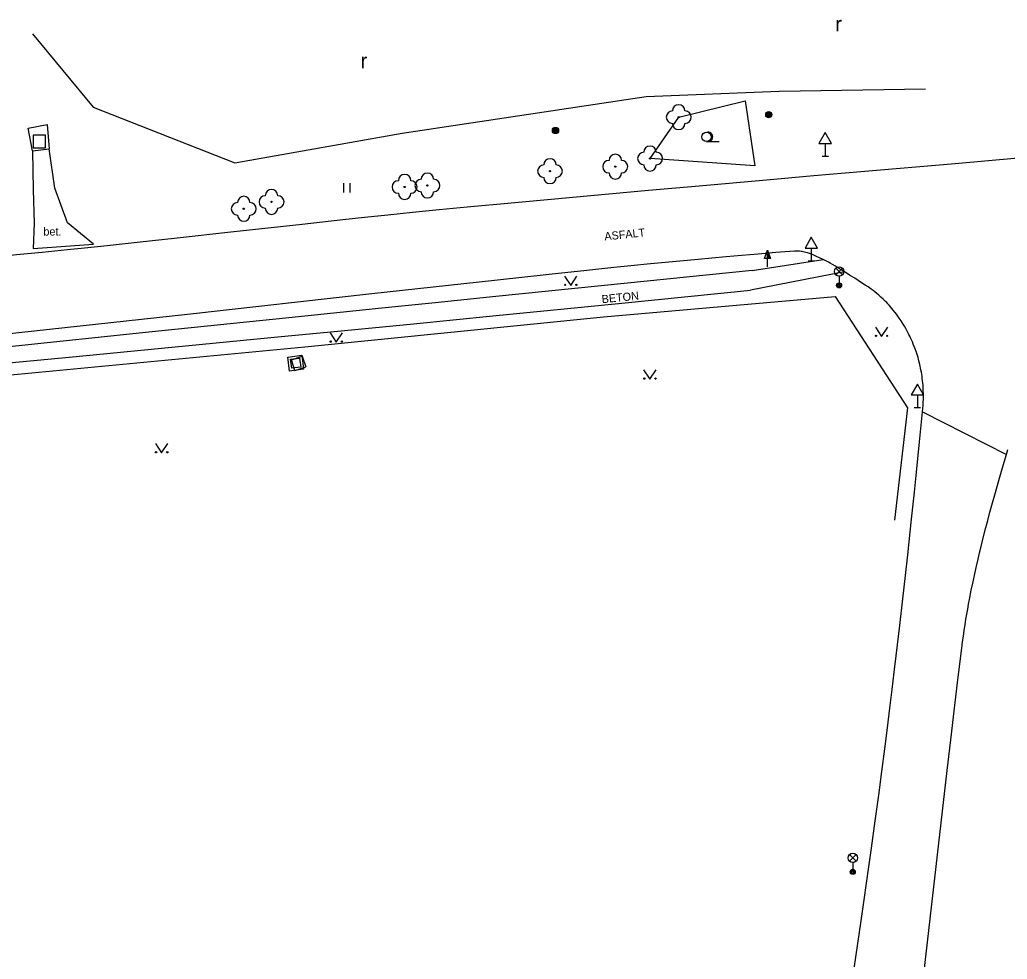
# Model space of a CAD drawing. Extents: x -541281 to -539153, y -1183881 to -1182141.
# Drawn here: x -539932.5 to -539853.2, y -1183251.4 to -1183176.1 of the extents above; entities that cross this region are included whole.
import ezdxf

# ---------------------------------------------------------------- set-up
doc = ezdxf.new("R2010")
doc.units = 0
for name, color, linetype in [('Vrstva 10', 7, 'Continuous'), ('Vrstva 11', 7, 'Continuous'), ('Vrstva 21', 7, 'Continuous'), ('Vrstva 22', 7, 'Continuous'), ('Vrstva 23', 7, 'Continuous'), ('Vrstva 25', 7, 'Continuous'), ('Vrstva 26', 7, 'Continuous'), ('Vrstva 33', 7, 'Continuous'), ('Vrstva 34', 7, 'Continuous'), ('Vrstva 36', 7, 'Continuous'), ('Vrstva 40', 7, 'Continuous'), ('Vrstva 7', 7, 'Continuous')]:
    doc.layers.add(name, color=color, linetype=linetype)

msp = doc.modelspace()

# ---------------------------------------------------------------- linework, layer by layer
at = {"layer": 'Vrstva 10'}
for p, q in [((-539852.324, -1183187.172), (-539857.371, -1183187.609)), ((-539857.371, -1183187.609), (-539864.941, -1183188.26)), ((-539872.51, -1183188.92), (-539877.926, -1183189.401)), ((-539877.926, -1183189.401), (-539881.987, -1183189.764)), ((-539888.079, -1183190.314), (-539894.17, -1183190.87)), ((-539881.987, -1183189.764), (-539888.079, -1183190.314)), ((-539909.795, -1183192.471), (-539915.522, -1183193.103)), ((-539883.41, -1183195.806), (-539884.78, -1183195.946)), ((-539894.36, -1183196.97), (-539904.21, -1183198.056)), ((-539904.21, -1183198.056), (-539918.985, -1183199.692)), ((-539918.985, -1183199.692), (-539926.372, -1183200.508)), ((-539926.372, -1183200.508), (-539933.76, -1183201.32)), ((-539910.943, -1183203.121), (-539909.821, -1183202.977)), ((-539910.799, -1183204.243), (-539910.943, -1183203.121)), ((-539910.719, -1183203.294), (-539909.994, -1183203.201)), ((-539909.994, -1183203.201), (-539909.901, -1183203.926)), ((-539909.821, -1183202.977), (-539909.677, -1183204.099)), ((-539910.626, -1183204.019), (-539910.719, -1183203.294)), ((-539909.901, -1183203.926), (-539910.626, -1183204.019)), ((-539909.677, -1183204.099), (-539910.799, -1183204.243)), ((-539860.649, -1183213.97), (-539860.481, -1183212.354)), ((-539861.822, -1183224.66), (-539861.577, -1183222.515)), ((-539863.029, -1183234.571), (-539862.813, -1183232.881)), ((-539859.898, -1183252.651), (-539858.404, -1183239.563))]:
    msp.add_line(p, q, dxfattribs=at)
for points in [[(-539864.941, -1183188.26), (-539868.726, -1183188.588), (-539872.51, -1183188.92)], [(-539894.17, -1183190.87), (-539895.376, -1183190.982), (-539896.544, -1183191.093), (-539898.806, -1183191.314), (-539900.926, -1183191.527), (-539902.913, -1183191.733)], [(-539902.913, -1183191.733), (-539904.776, -1183191.929), (-539906.522, -1183192.116), (-539909.795, -1183192.471)], [(-539915.522, -1183193.103), (-539919.817, -1183193.577), (-539923.039, -1183193.927), (-539925.456, -1183194.185)], [(-539925.456, -1183194.185), (-539927.269, -1183194.375), (-539928.629, -1183194.514), (-539930.669, -1183194.72), (-539932.71, -1183194.92), (-539934.224, -1183195.064)], [(-539874.518, -1183194.967), (-539875.758, -1183195.076), (-539876.921, -1183195.181), (-539878.012, -1183195.281), (-539880.056, -1183195.475), (-539881.845, -1183195.65), (-539883.41, -1183195.806)], [(-539865.851, -1183196.545), (-539866.06, -1183196.413), (-539866.27, -1183196.28), (-539866.48, -1183196.146), (-539866.662, -1183196.031), (-539866.981, -1183195.835), (-539867.223, -1183195.693), (-539867.407, -1183195.588), (-539867.547, -1183195.512), (-539867.76, -1183195.399), (-539867.98, -1183195.29), (-539868.26, -1183195.156), (-539868.506, -1183195.041), (-539868.723, -1183194.946), (-539868.913, -1183194.869), (-539869.081, -1183194.808), (-539869.229, -1183194.759), (-539869.358, -1183194.721), (-539869.472, -1183194.692), (-539869.572, -1183194.67), (-539869.659, -1183194.654), (-539869.736, -1183194.641), (-539869.871, -1183194.625), (-539869.973, -1183194.617), (-539870.049, -1183194.614), (-539870.165, -1183194.614), (-539870.28, -1183194.62), (-539871.784, -1183194.739), (-539873.195, -1183194.855), (-539874.518, -1183194.967)], [(-539884.78, -1183195.946), (-539887.176, -1183196.195), (-539888.973, -1183196.385), (-539891.667, -1183196.676), (-539894.36, -1183196.97)], [(-539860.124, -1183204.159), (-539860.154, -1183204.003), (-539860.186, -1183203.851), (-539860.22, -1183203.705), (-539860.29, -1183203.422), (-539860.363, -1183203.157), (-539860.438, -1183202.91), (-539860.514, -1183202.68), (-539860.59, -1183202.464), (-539860.666, -1183202.263), (-539860.741, -1183202.075), (-539860.815, -1183201.899), (-539860.887, -1183201.735), (-539860.958, -1183201.582), (-539861.027, -1183201.438), (-539861.093, -1183201.304), (-539861.224, -1183201.054), (-539861.344, -1183200.837), (-539861.454, -1183200.647), (-539861.554, -1183200.482), (-539861.644, -1183200.339), (-539861.725, -1183200.213), (-539861.872, -1183199.995), (-539861.986, -1183199.833), (-539862.074, -1183199.711), (-539862.21, -1183199.53), (-539862.35, -1183199.35), (-539862.46, -1183199.215), (-539862.567, -1183199.087), (-539862.672, -1183198.968), (-539862.775, -1183198.856), (-539862.875, -1183198.75), (-539862.972, -1183198.65), (-539863.067, -1183198.556), (-539863.16, -1183198.467), (-539863.341, -1183198.301), (-539863.513, -1183198.151), (-539863.675, -1183198.016), (-539863.829, -1183197.893), (-539863.975, -1183197.782), (-539864.112, -1183197.68), (-539864.372, -1183197.495), (-539864.602, -1183197.338), (-539864.805, -1183197.204), (-539865.164, -1183196.973), (-539865.437, -1183196.802), (-539865.851, -1183196.545)], [(-539860.481, -1183212.354), (-539860.233, -1183209.932), (-539859.99, -1183207.51), (-539859.966, -1183207.246), (-539859.949, -1183206.991), (-539859.937, -1183206.743), (-539859.93, -1183206.504), (-539859.928, -1183206.271), (-539859.93, -1183206.046), (-539859.936, -1183205.829), (-539859.946, -1183205.618), (-539859.96, -1183205.414), (-539859.976, -1183205.216), (-539859.995, -1183205.025), (-539860.017, -1183204.84), (-539860.041, -1183204.662), (-539860.066, -1183204.489), (-539860.094, -1183204.321), (-539860.124, -1183204.159)], [(-539855.674, -1183219.912), (-539855.544, -1183219.349), (-539855.419, -1183218.822), (-539855.298, -1183218.328), (-539855.184, -1183217.865), (-539854.962, -1183216.999), (-539854.763, -1183216.241), (-539854.585, -1183215.579), (-539854.426, -1183214.999), (-539854.143, -1183213.985), (-539853.926, -1183213.224), (-539853.596, -1183212.083), (-539853.26, -1183210.94), (-539853.14, -1183210.542)], [(-539861.577, -1183222.515), (-539861.367, -1183220.639), (-539861.186, -1183218.997), (-539860.876, -1183216.124), (-539860.649, -1183213.97)], [(-539856.231, -1183222.573), (-539856.088, -1183221.84), (-539855.946, -1183221.154), (-539855.808, -1183220.513), (-539855.674, -1183219.912)], [(-539857.521, -1183231.998), (-539857.189, -1183229.239), (-539856.85, -1183226.48), (-539856.786, -1183225.986), (-539856.721, -1183225.508), (-539856.653, -1183225.046), (-539856.584, -1183224.599), (-539856.515, -1183224.166), (-539856.444, -1183223.748), (-539856.373, -1183223.343), (-539856.302, -1183222.952), (-539856.231, -1183222.573)], [(-539862.813, -1183232.881), (-539862.615, -1183231.296), (-539862.433, -1183229.81), (-539862.264, -1183228.417), (-539862.109, -1183227.11), (-539861.822, -1183224.66)], [(-539858.404, -1183239.563), (-539858.026, -1183236.291), (-539857.738, -1183233.838), (-539857.521, -1183231.998)], [(-539864.26, -1183243.65), (-539864.1, -1183242.524), (-539863.796, -1183240.341), (-539863.517, -1183238.293), (-539863.263, -1183236.372), (-539863.029, -1183234.571)], [(-539865.618, -1183253.1), (-539864.938, -1183248.375), (-539864.26, -1183243.65)]]:
    msp.add_lwpolyline(points, dxfattribs=at)
at = {"layer": 'Vrstva 11'}
for p, q in [((-539873.68, -1183196.18), (-539867.98, -1183195.29)), ((-539873.68, -1183196.18), (-539883.96, -1183197.22)), ((-539866.27, -1183196.28), (-539873.81, -1183197.76)), ((-539883.96, -1183197.22), (-539894.24, -1183198.26)), ((-539884.145, -1183198.79), (-539873.81, -1183197.76)), ((-539903.396, -1183199.194), (-539910.872, -1183199.965)), ((-539894.48, -1183199.82), (-539884.145, -1183198.79)), ((-539910.872, -1183199.965), (-539922.086, -1183201.129)), ((-539907.229, -1183201.072), (-539900.854, -1183200.45)), ((-539922.086, -1183201.129), (-539933.3, -1183202.29)), ((-539928.482, -1183203.12), (-539911.48, -1183201.483)), ((-539911.48, -1183201.483), (-539907.229, -1183201.072)), ((-539933.34, -1183203.59), (-539928.482, -1183203.12)), ((-539859.99, -1183207.51), (-539853.26, -1183210.94))]:
    msp.add_line(p, q, dxfattribs=at)
for points in [[(-539931.43, -1183186.58), (-539931.79, -1183184.75), (-539930.27, -1183184.46), (-539930.1, -1183186.41)], [(-539931.43, -1183186.58), (-539930.1, -1183186.41)], [(-539931.43, -1183186.58), (-539931.37, -1183189.69), (-539931.3, -1183192.38), (-539931.37, -1183194.4), (-539926.55, -1183194.05), (-539928.63, -1183192.35), (-539929.64, -1183189.56), (-539930.1, -1183186.41)], [(-539894.24, -1183198.26), (-539899.123, -1183198.756), (-539903.396, -1183199.194)], [(-539900.854, -1183200.45), (-539897.667, -1183200.136), (-539894.48, -1183199.82)]]:
    msp.add_lwpolyline(points, dxfattribs=at)
at = {"layer": 'Vrstva 21'}
msp.add_lwpolyline([(-539879.57, -1183183.87), (-539874.24, -1183182.55), (-539873.46, -1183187.77), (-539881.87, -1183187.19), (-539879.57, -1183183.87)], dxfattribs=at)
at = {"layer": 'Vrstva 22'}
for centre in [(-539879.57, -1183183.87), (-539881.87, -1183187.19), (-539884.66, -1183187.84), (-539889.9, -1183188.2), (-539901.57, -1183189.47), (-539899.74, -1183189.35), (-539914.48, -1183191.22), (-539912.25, -1183190.67)]:
    msp.add_circle(centre, 0.05, dxfattribs=at)
for centre, start, end in [((-539880.07, -1183183.87), 90, 270), ((-539879.57, -1183183.37), 0, 180), ((-539879.07, -1183183.87), 270, 90), ((-539879.57, -1183184.37), 180, 0), ((-539881.87, -1183186.69), 0, 180), ((-539889.9, -1183187.7), 0, 180), ((-539885.16, -1183187.84), 90, 270), ((-539884.66, -1183187.34), 0, 180), ((-539884.16, -1183187.84), 270, 90), ((-539882.37, -1183187.19), 90, 270), ((-539881.37, -1183187.19), 270, 90), ((-539890.4, -1183188.2), 90, 270), ((-539889.4, -1183188.2), 270, 90), ((-539881.87, -1183187.69), 180, 0), ((-539901.57, -1183188.97), 0, 180), ((-539900.24, -1183189.35), 90, 270), ((-539899.74, -1183188.85), 0, 180), ((-539899.24, -1183189.35), 270, 90), ((-539889.9, -1183188.7), 180, 0), ((-539884.66, -1183188.34), 180, 0), ((-539912.25, -1183190.17), 0, 180), ((-539902.07, -1183189.47), 90, 270), ((-539901.07, -1183189.47), 270, 90), ((-539914.48, -1183190.72), 0, 180), ((-539912.75, -1183190.67), 90, 270), ((-539911.75, -1183190.67), 270, 90), ((-539901.57, -1183189.97), 180, 0), ((-539899.74, -1183189.85), 180, 0), ((-539914.98, -1183191.22), 90, 270), ((-539913.98, -1183191.22), 270, 90), ((-539912.25, -1183191.17), 180, 0), ((-539914.48, -1183191.72), 180, 0)]:
    msp.add_arc(centre, 0.5, start, end, dxfattribs=at)
at = {"layer": 'Vrstva 23'}
msp.add_lwpolyline([(-539931.43, -1183177.19), (-539926.56, -1183183.07), (-539915.2, -1183187.52), (-539901.76, -1183185.15), (-539882.17, -1183182.22), (-539871.52, -1183181.79), (-539859.76, -1183181.6)], dxfattribs=at)
at = {"layer": 'Vrstva 25'}
for p, q in [((-539872.692, -1183195.218), (-539872.44, -1183194.544)), ((-539872.44, -1183195.218), (-539872.692, -1183195.218)), ((-539872.44, -1183195.87), (-539872.44, -1183195.22))]:
    msp.add_line(p, q, dxfattribs=at)
for points in [[(-539872.19, -1183195.22), (-539872.44, -1183195.22), (-539872.44, -1183194.544), (-539872.44, -1183194.544)], [(-539872.247, -1183195.18), (-539872.4, -1183195.18), (-539872.4, -1183194.767)], [(-539872.305, -1183195.14), (-539872.36, -1183195.14), (-539872.36, -1183194.991)]]:
    msp.add_lwpolyline(points, close=True, dxfattribs=at)
for centre, radius in [((-539872.34, -1183183.66), 0.25), ((-539872.34, -1183183.66), 0.2), ((-539872.34, -1183183.66), 0.15), ((-539872.34, -1183183.66), 0.1), ((-539872.34, -1183183.66), 0.05), ((-539889.46, -1183184.94), 0.25), ((-539889.46, -1183184.94), 0.2), ((-539889.46, -1183184.94), 0.15), ((-539889.46, -1183184.94), 0.1), ((-539889.46, -1183184.94), 0.05)]:
    msp.add_circle(centre, radius, dxfattribs=at)
at = {"layer": 'Vrstva 26'}
msp.add_lwpolyline([(-539931.39, -1183186.32), (-539930.39, -1183186.32), (-539930.39, -1183185.32), (-539931.39, -1183185.32)], close=True, dxfattribs=at)
at = {"layer": 'Vrstva 33'}
for p, q in [((-539866.965, -1183196.51), (-539866.435, -1183195.98)), ((-539866.965, -1183195.98), (-539866.435, -1183196.51)), ((-539866.7, -1183196.62), (-539866.7, -1183197.37)), ((-539865.865, -1183243.58), (-539865.335, -1183243.05)), ((-539865.865, -1183243.05), (-539865.335, -1183243.58)), ((-539865.6, -1183243.69), (-539865.6, -1183244.44))]:
    msp.add_line(p, q, dxfattribs=at)
for centre, radius in [((-539866.7, -1183196.245), 0.375), ((-539866.7, -1183197.37), 0.2), ((-539866.7, -1183197.37), 0.145), ((-539866.7, -1183197.37), 0.0876), ((-539865.6, -1183243.315), 0.375), ((-539865.6, -1183244.44), 0.2), ((-539865.6, -1183244.44), 0.145), ((-539865.6, -1183244.44), 0.0876)]:
    msp.add_circle(centre, radius, dxfattribs=at)
at = {"layer": 'Vrstva 34'}
for p, q in [((-539867.81, -1183185.972), (-539867.81, -1183186.99)), ((-539868.06, -1183186.99), (-539867.56, -1183186.99)), ((-539868.93, -1183194.372), (-539868.93, -1183195.39)), ((-539869.18, -1183195.39), (-539868.68, -1183195.39)), ((-539860.41, -1183206.152), (-539860.41, -1183207.17)), ((-539860.66, -1183207.17), (-539860.16, -1183207.17))]:
    msp.add_line(p, q, dxfattribs=at)
for points in [[(-539868.31, -1183185.972), (-539867.31, -1183185.972), (-539867.81, -1183185.106)], [(-539869.43, -1183194.372), (-539868.43, -1183194.372), (-539868.93, -1183193.506)], [(-539860.91, -1183206.152), (-539859.91, -1183206.152), (-539860.41, -1183205.286)]]:
    msp.add_lwpolyline(points, close=True, dxfattribs=at)
at = {"layer": 'Vrstva 36'}
for p, q in [((-539877.334, -1183185.831), (-539876.334, -1183185.831)), ((-539906.447, -1183189.926), (-539906.447, -1183189.176)), ((-539905.947, -1183189.926), (-539905.947, -1183189.176))]:
    msp.add_line(p, q, dxfattribs=at)
for points in [[(-539888.734, -1183196.628), (-539888.234, -1183197.378), (-539887.734, -1183196.628)], [(-539863.784, -1183200.716), (-539863.284, -1183201.466), (-539862.784, -1183200.716)], [(-539907.554, -1183201.179), (-539907.054, -1183201.929), (-539906.554, -1183201.179)], [(-539882.384, -1183204.147), (-539881.884, -1183204.897), (-539881.384, -1183204.147)], [(-539921.57, -1183210.061), (-539921.07, -1183210.811), (-539920.57, -1183210.061)]]:
    msp.add_lwpolyline(points, dxfattribs=at)
for centre, radius in [((-539877.334, -1183185.455), 0.375), ((-539888.685, -1183197.328), 0.05), ((-539887.785, -1183197.328), 0.05), ((-539863.734, -1183201.416), 0.05), ((-539862.835, -1183201.416), 0.05), ((-539907.504, -1183201.879), 0.05), ((-539906.605, -1183201.879), 0.05), ((-539882.334, -1183204.847), 0.05), ((-539881.435, -1183204.847), 0.05), ((-539921.52, -1183210.76), 0.05), ((-539920.621, -1183210.76), 0.05)]:
    msp.add_circle(centre, radius, dxfattribs=at)
msp.add_arc((-539877.209, -1183185.455), 0.375, 260.40593, 99.59407, dxfattribs=at)
at = {"layer": 'Vrstva 7'}
for p, q in [((-539933.17, -1183204.55), (-539909.57, -1183202.3)), ((-539910.378, -1183204.195), (-539909.498, -1183203.905))]:
    msp.add_line(p, q, dxfattribs=at)
for points in [[(-539909.57, -1183202.3), (-539885.61, -1183199.88), (-539867.02, -1183198.26), (-539861.2, -1183207.19), (-539862.25, -1183216.22)], [(-539910.378, -1183204.195), (-539910.66, -1183203.34), (-539909.78, -1183203.05), (-539909.498, -1183203.905)]]:
    msp.add_lwpolyline(points, dxfattribs=at)

# ---------------------------------------------------------------- texts
at = {"layer": 'Vrstva 36'}
for p in [(-539867.008, -1183176.989), (-539905.105, -1183179.945)]:
    msp.add_text('r', height=1.2, dxfattribs=at).set_placement(p)
at = {"layer": 'Vrstva 40'}
msp.add_text('bet.', height=0.65, dxfattribs=at).set_placement((-539930.564, -1183193.369))
for s, rotation, p in [('ASFALT', 5.84231, (-539885.504, -1183193.767)), ('BETON', 5.69138, (-539885.72, -1183198.804))]:
    msp.add_text(s, height=0.65, rotation=rotation, dxfattribs=at).set_placement(p)

doc.saveas('drawing.dxf')
